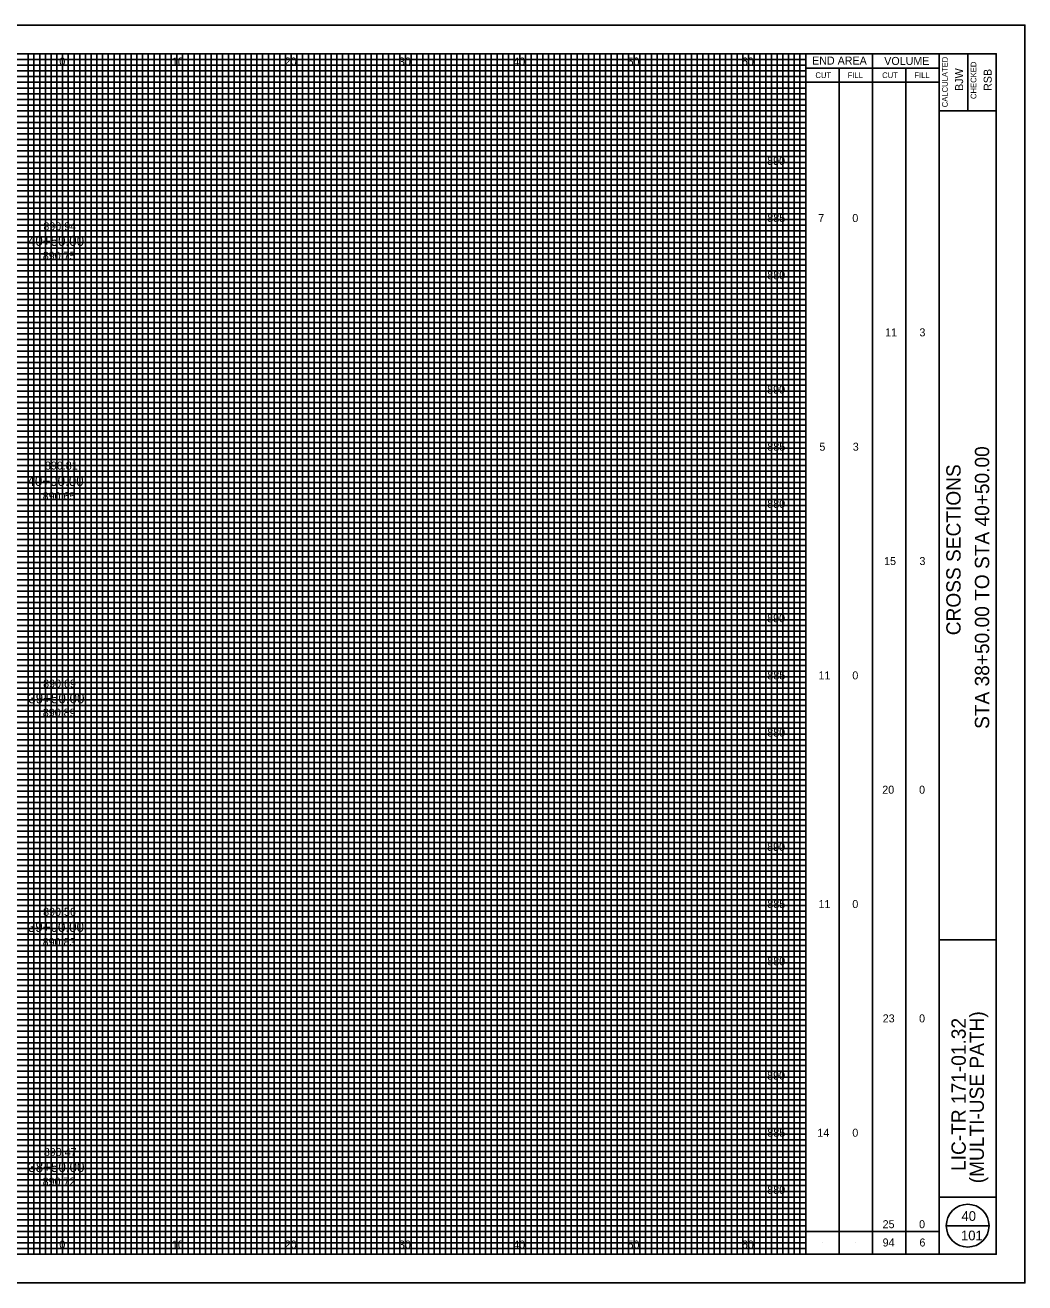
# Model space of a CAD drawing. Extents: x -10 to 160, y -2 to 2522.
# Drawn here: x 72.6 to 160, y 1377.5 to 1487.5 of the extents above; entities that cross this region are included whole.
import ezdxf

# ---------------------------------------------------------------- set-up
doc = ezdxf.new("R2010")
doc.units = 0
for name, color, linetype in [('GK_Cells', 7, 'Continuous'), ('GK_Patterns', 7, 'Continuous'), ('TX_P_10', 7, 'Continuous'), ('TX_X_10', 7, 'Continuous'), ('XS_P_Finished_Grade_Seeded', 7, 'Continuous'), ('XS_P_Pavt_Surface', 7, 'Continuous'), ('XS_P_Subgrade', 7, 'Continuous'), ('XS_X_Ground_Line', 7, 'Continuous')]:
    doc.layers.add(name, color=color, linetype=linetype)

msp = doc.modelspace()

# ---------------------------------------------------------------- linework, layer by layer
at = {"layer": 'GK_Cells'}
msp.add_lwpolyline([(-10, 1377.5), (160, 1377.5), (160, 1487.5), (-10, 1487.5)], close=True, dxfattribs=at)
at = {"layer": 'TX_P_10'}
for p, q in [((140.83, 1380), (140.83, 1485)), ((146.67, 1380), (146.67, 1485)), ((140.83, 1483.75), (152.5, 1483.75)), ((143.75, 1380), (143.75, 1483.75)), ((149.58, 1380), (149.58, 1483.75)), ((140.83, 1482.5), (152.5, 1482.5)), ((140.83, 1382), (152.5, 1382)), ((153.12, 1382.5), (156.88, 1382.5)), ((142.29, 1381), (142.29, 1381)), ((145.21, 1381), (145.21, 1381)), ((148.12, 1381), (148.12, 1381)), ((151.04, 1381), (151.04, 1381))]:
    msp.add_line(p, q, dxfattribs=at)
msp.add_circle((155, 1382.5), 1.87, dxfattribs=at)
at = {"layer": 'TX_X_10'}
for p, q in [((75.83, 1380), (75.83, 1485)), ((80.83, 1380), (80.83, 1485)), ((85.83, 1380), (85.83, 1485)), ((90.83, 1380), (90.83, 1485)), ((95.83, 1380), (95.83, 1485)), ((100.83, 1380), (100.83, 1485)), ((105.83, 1380), (105.83, 1485)), ((110.83, 1380), (110.83, 1485)), ((115.83, 1380), (115.83, 1485)), ((120.83, 1380), (120.83, 1485)), ((125.83, 1380), (125.83, 1485)), ((130.83, 1380), (130.83, 1485)), ((135.83, 1380), (135.83, 1485)), ((5.83, 1480), (140.83, 1480)), ((5.83, 1475), (140.83, 1475)), ((5.83, 1470), (140.83, 1470)), ((5.83, 1465), (140.83, 1465)), ((5.83, 1460), (140.83, 1460)), ((5.83, 1455), (140.83, 1455)), ((5.83, 1450), (140.83, 1450)), ((5.83, 1445), (140.83, 1445)), ((5.83, 1440), (140.83, 1440)), ((5.83, 1435), (140.83, 1435)), ((5.83, 1430), (140.83, 1430)), ((5.83, 1425), (140.83, 1425)), ((5.83, 1420), (140.83, 1420)), ((5.83, 1415), (140.83, 1415)), ((5.83, 1410), (140.83, 1410)), ((5.83, 1405), (140.83, 1405)), ((5.83, 1400), (140.83, 1400)), ((5.83, 1395), (140.83, 1395)), ((5.83, 1390), (140.83, 1390)), ((5.83, 1385), (140.83, 1385))]:
    msp.add_line(p, q, dxfattribs=at)
at = {"layer": 'XS_P_Pavt_Surface'}
for p, q in [((152.5, 1380), (152.5, 1485)), ((155, 1485), (155, 1480)), ((152.5, 1480), (157.5, 1480)), ((152.5, 1407.5), (157.5, 1407.5)), ((152.5, 1385), (157.5, 1385))]:
    msp.add_line(p, q, dxfattribs=at)
msp.add_lwpolyline([(0, 1485), (157.5, 1485), (157.5, 1380), (0, 1380)], close=True, dxfattribs=at)
at = {"layer": 'XS_X_Ground_Line'}
for p, q in [((72.83, 1380), (72.83, 1485)), ((73.33, 1380), (73.33, 1485)), ((73.83, 1380), (73.83, 1485)), ((74.33, 1380), (74.33, 1485)), ((74.83, 1380), (74.83, 1485)), ((75.33, 1380), (75.33, 1485)), ((76.33, 1380), (76.33, 1485)), ((76.83, 1380), (76.83, 1485)), ((77.33, 1380), (77.33, 1485)), ((77.83, 1380), (77.83, 1485)), ((78.33, 1380), (78.33, 1485)), ((78.83, 1380), (78.83, 1485)), ((79.33, 1380), (79.33, 1485)), ((79.83, 1380), (79.83, 1485)), ((80.33, 1380), (80.33, 1485)), ((81.33, 1380), (81.33, 1485)), ((81.83, 1380), (81.83, 1485)), ((82.33, 1380), (82.33, 1485)), ((82.83, 1380), (82.83, 1485)), ((83.33, 1380), (83.33, 1485)), ((83.83, 1380), (83.83, 1485)), ((84.33, 1380), (84.33, 1485)), ((84.83, 1380), (84.83, 1485)), ((85.33, 1380), (85.33, 1485)), ((86.33, 1380), (86.33, 1485)), ((86.83, 1380), (86.83, 1485)), ((87.33, 1380), (87.33, 1485)), ((87.83, 1380), (87.83, 1485)), ((88.33, 1380), (88.33, 1485)), ((88.83, 1380), (88.83, 1485)), ((89.33, 1380), (89.33, 1485)), ((89.83, 1380), (89.83, 1485)), ((90.33, 1380), (90.33, 1485)), ((91.33, 1380), (91.33, 1485)), ((91.83, 1380), (91.83, 1485)), ((92.33, 1380), (92.33, 1485)), ((92.83, 1380), (92.83, 1485)), ((93.33, 1380), (93.33, 1485)), ((93.83, 1380), (93.83, 1485)), ((94.33, 1380), (94.33, 1485)), ((94.83, 1380), (94.83, 1485)), ((95.33, 1380), (95.33, 1485)), ((96.33, 1380), (96.33, 1485)), ((96.83, 1380), (96.83, 1485)), ((97.33, 1380), (97.33, 1485)), ((97.83, 1380), (97.83, 1485)), ((98.33, 1380), (98.33, 1485)), ((98.83, 1380), (98.83, 1485)), ((99.33, 1380), (99.33, 1485)), ((99.83, 1380), (99.83, 1485)), ((100.33, 1380), (100.33, 1485)), ((101.33, 1380), (101.33, 1485)), ((101.83, 1380), (101.83, 1485)), ((102.33, 1380), (102.33, 1485)), ((102.83, 1380), (102.83, 1485)), ((103.33, 1380), (103.33, 1485)), ((103.83, 1380), (103.83, 1485)), ((104.33, 1380), (104.33, 1485)), ((104.83, 1380), (104.83, 1485)), ((105.33, 1380), (105.33, 1485)), ((106.33, 1380), (106.33, 1485)), ((106.83, 1380), (106.83, 1485)), ((107.33, 1380), (107.33, 1485)), ((107.83, 1380), (107.83, 1485)), ((108.33, 1380), (108.33, 1485)), ((108.83, 1380), (108.83, 1485)), ((109.33, 1380), (109.33, 1485)), ((109.83, 1380), (109.83, 1485)), ((110.33, 1380), (110.33, 1485)), ((111.33, 1380), (111.33, 1485)), ((111.83, 1380), (111.83, 1485)), ((112.33, 1380), (112.33, 1485)), ((112.83, 1380), (112.83, 1485)), ((113.33, 1380), (113.33, 1485)), ((113.83, 1380), (113.83, 1485)), ((114.33, 1380), (114.33, 1485)), ((114.83, 1380), (114.83, 1485)), ((115.33, 1380), (115.33, 1485)), ((116.33, 1380), (116.33, 1485)), ((116.83, 1380), (116.83, 1485)), ((117.33, 1380), (117.33, 1485)), ((117.83, 1380), (117.83, 1485)), ((118.33, 1380), (118.33, 1485)), ((118.83, 1380), (118.83, 1485)), ((119.33, 1380), (119.33, 1485)), ((119.83, 1380), (119.83, 1485)), ((120.33, 1380), (120.33, 1485)), ((121.33, 1380), (121.33, 1485)), ((121.83, 1380), (121.83, 1485)), ((122.33, 1380), (122.33, 1485)), ((122.83, 1380), (122.83, 1485)), ((123.33, 1380), (123.33, 1485)), ((123.83, 1380), (123.83, 1485)), ((124.33, 1380), (124.33, 1485)), ((124.83, 1380), (124.83, 1485)), ((125.33, 1380), (125.33, 1485)), ((126.33, 1380), (126.33, 1485)), ((126.83, 1380), (126.83, 1485)), ((127.33, 1380), (127.33, 1485)), ((127.83, 1380), (127.83, 1485)), ((128.33, 1380), (128.33, 1485)), ((128.83, 1380), (128.83, 1485)), ((129.33, 1380), (129.33, 1485)), ((129.83, 1380), (129.83, 1485)), ((130.33, 1380), (130.33, 1485)), ((131.33, 1380), (131.33, 1485)), ((131.83, 1380), (131.83, 1485)), ((132.33, 1380), (132.33, 1485)), ((132.83, 1380), (132.83, 1485)), ((133.33, 1380), (133.33, 1485)), ((133.83, 1380), (133.83, 1485)), ((134.33, 1380), (134.33, 1485)), ((134.83, 1380), (134.83, 1485)), ((135.33, 1380), (135.33, 1485)), ((136.33, 1380), (136.33, 1485)), ((136.83, 1380), (136.83, 1485)), ((137.33, 1380), (137.33, 1485)), ((137.83, 1380), (137.83, 1485)), ((138.33, 1380), (138.33, 1485)), ((138.83, 1380), (138.83, 1485)), ((139.33, 1380), (139.33, 1485)), ((139.83, 1380), (139.83, 1485)), ((140.33, 1380), (140.33, 1485)), ((5.83, 1484.5), (140.83, 1484.5)), ((5.83, 1484), (140.83, 1484)), ((5.83, 1483.5), (140.83, 1483.5)), ((5.83, 1483), (140.83, 1483)), ((5.83, 1482.5), (140.83, 1482.5)), ((5.83, 1482), (140.83, 1482)), ((5.83, 1481.5), (140.83, 1481.5)), ((5.83, 1481), (140.83, 1481)), ((5.83, 1480.5), (140.83, 1480.5)), ((5.83, 1479.5), (140.83, 1479.5)), ((5.83, 1479), (140.83, 1479)), ((5.83, 1478.5), (140.83, 1478.5)), ((5.83, 1478), (140.83, 1478)), ((5.83, 1477.5), (140.83, 1477.5)), ((5.83, 1477), (140.83, 1477)), ((5.83, 1476.5), (140.83, 1476.5)), ((5.83, 1476), (140.83, 1476)), ((5.83, 1475.5), (140.83, 1475.5)), ((5.83, 1474.5), (140.83, 1474.5)), ((5.83, 1474), (140.83, 1474)), ((5.83, 1473.5), (140.83, 1473.5)), ((5.83, 1473), (140.83, 1473)), ((5.83, 1472.5), (140.83, 1472.5)), ((5.83, 1472), (140.83, 1472)), ((5.83, 1471.5), (140.83, 1471.5)), ((5.83, 1471), (140.83, 1471)), ((5.83, 1470.5), (140.83, 1470.5)), ((5.83, 1469.5), (140.83, 1469.5)), ((5.83, 1469), (140.83, 1469)), ((5.83, 1468.5), (140.83, 1468.5)), ((5.83, 1468), (140.83, 1468)), ((5.83, 1467.5), (140.83, 1467.5)), ((5.83, 1467), (140.83, 1467)), ((5.83, 1466.5), (140.83, 1466.5)), ((5.83, 1466), (140.83, 1466)), ((5.83, 1465.5), (140.83, 1465.5)), ((5.83, 1464.5), (140.83, 1464.5)), ((5.83, 1464), (140.83, 1464)), ((5.83, 1463.5), (140.83, 1463.5)), ((5.83, 1463), (140.83, 1463)), ((5.83, 1462.5), (140.83, 1462.5)), ((5.83, 1462), (140.83, 1462)), ((5.83, 1461.5), (140.83, 1461.5)), ((5.83, 1461), (140.83, 1461)), ((5.83, 1460.5), (140.83, 1460.5)), ((5.83, 1459.5), (140.83, 1459.5)), ((5.83, 1459), (140.83, 1459)), ((5.83, 1458.5), (140.83, 1458.5)), ((5.83, 1458), (140.83, 1458)), ((5.83, 1457.5), (140.83, 1457.5)), ((5.83, 1457), (140.83, 1457)), ((5.83, 1456.5), (140.83, 1456.5)), ((5.83, 1456), (140.83, 1456)), ((5.83, 1455.5), (140.83, 1455.5)), ((5.83, 1454.5), (140.83, 1454.5)), ((5.83, 1454), (140.83, 1454)), ((5.83, 1453.5), (140.83, 1453.5)), ((5.83, 1453), (140.83, 1453)), ((5.83, 1452.5), (140.83, 1452.5)), ((5.83, 1452), (140.83, 1452)), ((5.83, 1451.5), (140.83, 1451.5)), ((5.83, 1451), (140.83, 1451)), ((5.83, 1450.5), (140.83, 1450.5)), ((5.83, 1449.5), (140.83, 1449.5)), ((5.83, 1449), (140.83, 1449)), ((5.83, 1448.5), (140.83, 1448.5)), ((5.83, 1448), (140.83, 1448)), ((5.83, 1447.5), (140.83, 1447.5)), ((5.83, 1447), (140.83, 1447)), ((5.83, 1446.5), (140.83, 1446.5)), ((5.83, 1446), (140.83, 1446)), ((5.83, 1445.5), (140.83, 1445.5)), ((5.83, 1444.5), (140.83, 1444.5)), ((5.83, 1444), (140.83, 1444)), ((5.83, 1443.5), (140.83, 1443.5)), ((5.83, 1443), (140.83, 1443)), ((5.83, 1442.5), (140.83, 1442.5)), ((5.83, 1442), (140.83, 1442)), ((5.83, 1441.5), (140.83, 1441.5)), ((5.83, 1441), (140.83, 1441)), ((5.83, 1440.5), (140.83, 1440.5)), ((5.83, 1439.5), (140.83, 1439.5)), ((5.83, 1439), (140.83, 1439)), ((5.83, 1438.5), (140.83, 1438.5)), ((5.83, 1438), (140.83, 1438)), ((5.83, 1437.5), (140.83, 1437.5)), ((5.83, 1437), (140.83, 1437)), ((5.83, 1436.5), (140.83, 1436.5)), ((5.83, 1436), (140.83, 1436)), ((5.83, 1435.5), (140.83, 1435.5)), ((5.83, 1434.5), (140.83, 1434.5)), ((5.83, 1434), (140.83, 1434)), ((5.83, 1433.5), (140.83, 1433.5)), ((5.83, 1433), (140.83, 1433)), ((5.83, 1432.5), (140.83, 1432.5)), ((5.83, 1432), (140.83, 1432)), ((5.83, 1431.5), (140.83, 1431.5)), ((5.83, 1431), (140.83, 1431)), ((5.83, 1430.5), (140.83, 1430.5)), ((5.83, 1429.5), (140.83, 1429.5)), ((5.83, 1429), (140.83, 1429)), ((5.83, 1428.5), (140.83, 1428.5)), ((5.83, 1428), (140.83, 1428)), ((5.83, 1427.5), (140.83, 1427.5)), ((5.83, 1427), (140.83, 1427)), ((5.83, 1426.5), (140.83, 1426.5)), ((5.83, 1426), (140.83, 1426)), ((5.83, 1425.5), (140.83, 1425.5)), ((5.83, 1424.5), (140.83, 1424.5)), ((5.83, 1424), (140.83, 1424)), ((5.83, 1423.5), (140.83, 1423.5)), ((5.83, 1423), (140.83, 1423)), ((5.83, 1422.5), (140.83, 1422.5)), ((5.83, 1422), (140.83, 1422)), ((5.83, 1421.5), (140.83, 1421.5)), ((5.83, 1421), (140.83, 1421)), ((5.83, 1420.5), (140.83, 1420.5)), ((5.83, 1419.5), (140.83, 1419.5)), ((5.83, 1419), (140.83, 1419)), ((5.83, 1418.5), (140.83, 1418.5)), ((5.83, 1418), (140.83, 1418)), ((5.83, 1417.5), (140.83, 1417.5)), ((5.83, 1417), (140.83, 1417)), ((5.83, 1416.5), (140.83, 1416.5)), ((5.83, 1416), (140.83, 1416)), ((5.83, 1415.5), (140.83, 1415.5)), ((5.83, 1414.5), (140.83, 1414.5)), ((5.83, 1414), (140.83, 1414)), ((5.83, 1413.5), (140.83, 1413.5)), ((5.83, 1413), (140.83, 1413)), ((5.83, 1412.5), (140.83, 1412.5)), ((5.83, 1412), (140.83, 1412)), ((5.83, 1411.5), (140.83, 1411.5)), ((5.83, 1411), (140.83, 1411)), ((5.83, 1410.5), (140.83, 1410.5)), ((5.83, 1409.5), (140.83, 1409.5)), ((5.83, 1409), (140.83, 1409)), ((5.83, 1408.5), (140.83, 1408.5)), ((5.83, 1408), (140.83, 1408)), ((5.83, 1407.5), (140.83, 1407.5)), ((5.83, 1407), (140.83, 1407)), ((5.83, 1406.5), (140.83, 1406.5)), ((5.83, 1406), (140.83, 1406)), ((5.83, 1405.5), (140.83, 1405.5)), ((5.83, 1404.5), (140.83, 1404.5)), ((5.83, 1404), (140.83, 1404)), ((5.83, 1403.5), (140.83, 1403.5)), ((5.83, 1403), (140.83, 1403)), ((5.83, 1402.5), (140.83, 1402.5)), ((5.83, 1402), (140.83, 1402)), ((5.83, 1401.5), (140.83, 1401.5)), ((5.83, 1401), (140.83, 1401)), ((5.83, 1400.5), (140.83, 1400.5)), ((5.83, 1399.5), (140.83, 1399.5)), ((5.83, 1399), (140.83, 1399)), ((5.83, 1398.5), (140.83, 1398.5)), ((5.83, 1398), (140.83, 1398)), ((5.83, 1397.5), (140.83, 1397.5)), ((5.83, 1397), (140.83, 1397)), ((5.83, 1396.5), (140.83, 1396.5)), ((5.83, 1396), (140.83, 1396)), ((5.83, 1395.5), (140.83, 1395.5)), ((5.83, 1394.5), (140.83, 1394.5)), ((5.83, 1394), (140.83, 1394)), ((5.83, 1393.5), (140.83, 1393.5)), ((5.83, 1393), (140.83, 1393)), ((5.83, 1392.5), (140.83, 1392.5)), ((5.83, 1392), (140.83, 1392)), ((5.83, 1391.5), (140.83, 1391.5)), ((5.83, 1391), (140.83, 1391)), ((5.83, 1390.5), (140.83, 1390.5)), ((5.83, 1389.5), (140.83, 1389.5)), ((5.83, 1389), (140.83, 1389)), ((5.83, 1388.5), (140.83, 1388.5)), ((5.83, 1388), (140.83, 1388)), ((5.83, 1387.5), (140.83, 1387.5)), ((5.83, 1387), (140.83, 1387)), ((5.83, 1386.5), (140.83, 1386.5)), ((5.83, 1386), (140.83, 1386)), ((5.83, 1385.5), (140.83, 1385.5)), ((5.83, 1384.5), (140.83, 1384.5)), ((5.83, 1384), (140.83, 1384)), ((5.83, 1383.5), (140.83, 1383.5)), ((5.83, 1383), (140.83, 1383)), ((5.83, 1382.5), (140.83, 1382.5)), ((5.83, 1382), (140.83, 1382)), ((5.83, 1381.5), (140.83, 1381.5)), ((5.83, 1381), (140.83, 1381)), ((5.83, 1380.5), (140.83, 1380.5))]:
    msp.add_line(p, q, dxfattribs=at)

# ---------------------------------------------------------------- texts
at = {"layer": 'GK_Patterns'}
for s, height, p in [('0', 0.7, (75.55, 1483.97)), ('0', 0.7, (75.55, 1483.97)), ('10', 0.7, (85.39, 1483.97)), ('20', 0.7, (95.26, 1483.97)), ('30', 0.7, (105.25, 1483.97)), ('40', 0.7, (115.25, 1483.97)), ('50', 0.7, (125.25, 1483.97)), ('60', 0.7, (135.25, 1483.97)), ('890', 0.7, (137.46, 1475.28)), ('885', 0.7, (137.48, 1470.28)), ('7', 0.7, (141.93, 1470.28)), ('0', 0.7, (144.91, 1470.28)), ('40+50.00', 0.875, (72.8, 1468.19)), ('880', 0.7, (137.47, 1465.28)), ('11', 0.7, (147.78, 1460.28)), ('3', 0.7, (150.78, 1460.28)), ('890', 0.7, (137.46, 1455.28)), ('885', 0.7, (137.48, 1450.28)), ('5', 0.7, (142.03, 1450.28)), ('3', 0.7, (144.95, 1450.28)), ('40+00.00', 0.875, (72.76, 1447.19)), ('880', 0.7, (137.47, 1445.28)), ('15', 0.7, (147.69, 1440.28)), ('3', 0.7, (150.78, 1440.28)), ('890', 0.7, (137.46, 1435.28)), ('885', 0.7, (137.48, 1430.28)), ('11', 0.7, (141.95, 1430.28)), ('0', 0.7, (144.91, 1430.28)), ('39+50.00', 0.875, (72.83, 1428.19)), ('880', 0.7, (137.47, 1425.28)), ('20', 0.7, (147.53, 1420.28)), ('0', 0.7, (150.75, 1420.28)), ('890', 0.7, (137.46, 1415.28)), ('885', 0.7, (137.48, 1410.28)), ('11', 0.7, (141.95, 1410.28)), ('0', 0.7, (144.91, 1410.28)), ('39+00.00', 0.875, (72.79, 1408.19)), ('880', 0.7, (137.47, 1405.28)), ('23', 0.7, (147.57, 1400.28)), ('0', 0.7, (150.75, 1400.28)), ('890', 0.7, (137.46, 1395.28)), ('885', 0.7, (137.48, 1390.28)), ('14', 0.7, (141.85, 1390.28)), ('0', 0.7, (144.91, 1390.28)), ('38+50.00', 0.875, (72.83, 1387.19)), ('880', 0.7, (137.47, 1385.28)), ('25', 0.7, (147.56, 1382.28)), ('0', 0.7, (150.75, 1382.28)), ('0', 0.7, (75.55, 1380.5)), ('0', 0.7, (75.55, 1380.5)), ('10', 0.7, (85.39, 1380.5)), ('20', 0.7, (95.26, 1380.5)), ('30', 0.7, (105.25, 1380.5)), ('40', 0.7, (115.25, 1380.5)), ('50', 0.7, (125.25, 1380.5)), ('60', 0.7, (135.25, 1380.5)), ('94', 0.7, (147.56, 1380.68)), ('6', 0.7, (150.78, 1380.68))]:
    msp.add_text(s, height=height, dxfattribs=at).set_placement(p)
at = {"layer": 'TX_P_10'}
for s, height, p in [('END AREA', 0.7, (141.39, 1484.05)), ('VOLUME', 0.7, (147.7, 1484.02)), ('CUT', 0.5, (141.68, 1482.87)), ('FILL', 0.5, (144.5, 1482.87)), ('CUT', 0.5, (147.52, 1482.87)), ('FILL', 0.5, (150.34, 1482.87)), ('40', 0.85, (154.46, 1382.92)), ('101', 0.85, (154.42, 1381.22))]:
    msp.add_text(s, height=height, dxfattribs=at).set_placement(p)
for s, height, p in [('CALCULATED', 0.5, (153.26, 1480.32)), ('CHECKED', 0.5, (155.76, 1481.04)), ('BJW', 0.7, (154.6, 1481.75)), ('RSB', 0.7, (157.1, 1481.75)), ('STA 38+50.00 TO STA 40+50.00', 1.25, (156.88, 1425.95)), ('CROSS SECTIONS', 1.25, (154.38, 1434.14)), ('LIC-TR 171-01.32', 1.25, (154.83, 1387.29)), ('(MULTI-USE PATH)', 1.25, (156.42, 1386.21))]:
    msp.add_text(s, height=height, rotation=90, dxfattribs=at).set_placement(p)
at = {"layer": 'XS_P_Finished_Grade_Seeded'}
for s, p in [('890.75', (74.1, 1466.98)), ('890.65', (74.09, 1445.95)), ('890.89', (74.1, 1427.02)), ('890.83', (74.09, 1406.95)), ('890.72', (74.09, 1386.01))]:
    msp.add_text(s, height=0.7, dxfattribs=at).set_placement(p)
at = {"layer": 'XS_P_Subgrade'}
for s, p in [('890.94', (74.15, 1469.56)), ('890.81', (74.29, 1448.63)), ('890.69', (74.13, 1429.56)), ('890.56', (74.13, 1409.6)), ('890.47', (74.19, 1388.59))]:
    msp.add_text(s, height=0.7, dxfattribs=at).set_placement(p)

doc.saveas('drawing.dxf')
